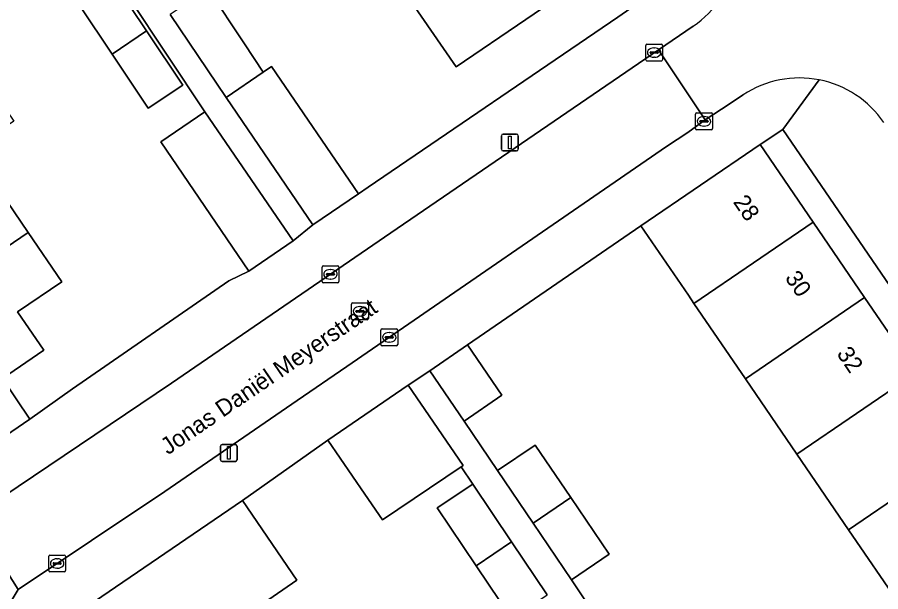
# Model space of a CAD drawing. Extents: x 157445 to 158888, y 383061 to 384688.
# Drawn here: x 158205.2 to 158256.4, y 383877.8 to 383911.9 of the extents above; entities that cross this region are included whole.
import ezdxf

# ---------------------------------------------------------------- set-up
doc = ezdxf.new("R2010")
doc.units = 0
for name, color, linetype in [('IMGEO_Erf', 7, 'Continuous'), ('IMGEO_Kolk', 7, 'Continuous'), ('IMGEO_Lichtmast', 7, 'Continuous'), ('IMGEO_Muur', 7, 'Continuous'), ('IMGEO_Openbare_ruimte_label', 7, 'Continuous'), ('IMGEO_Pand', 7, 'Continuous'), ('IMGEO_Pand_nummerreeks', 7, 'Continuous'), ('IMGEO_Rijbaan_lokaal_open', 7, 'Continuous'), ('IMGEO_Rioolput', 7, 'Continuous'), ('IMGEO_Voetpad_open', 7, 'Continuous')]:
    doc.layers.add(name, color=color, linetype=linetype)

msp = doc.modelspace()

# ---------------------------------------------------------------- linework, layer by layer
at = {"layer": 'IMGEO_Erf'}
for points in [[(158208.248, 383962.191), (158206.464, 383960.817), (158207.747, 383959.227), (158208.617, 383959.821), (158212.084, 383954.74), (158215.532, 383949.688), (158218.839, 383944.841), (158222.349, 383939.698), (158225.846, 383934.573), (158229.146, 383929.736), (158232.638, 383924.618), (158235.983, 383919.716), (158239.475, 383914.599), (158231.215, 383908.963), (158228.397, 383913.094), (158227.724, 383914.08), (158230.286, 383915.828), (158226.932, 383920.725), (158223.432, 383925.836), (158221.116, 383924.256), (158217.816, 383929.093), (158214.319, 383934.218)], [(158216.496, 383913.605), (158218.66, 383910.333), (158219.772, 383908.651), (158220.259, 383908.984), (158225.416, 383901.438), (158225.999, 383901.836), (158240.803, 383911.908), (158243.26, 383913.632)], [(158282.821, 383858.177), (158250.603, 383905.26), (158249.254, 383904.367), (158252.397, 383899.761), (158255.454, 383895.281), (158258.512, 383890.8)], [(158257.552, 383877.012), (158254.495, 383881.493), (158251.438, 383885.973), (158248.38, 383890.454), (158245.323, 383894.934), (158244.999, 383895.409), (158242.18, 383899.539), (158231.893, 383892.465), (158233.935, 383889.491), (158231.689, 383887.95), (158233.67, 383885.007), (158235.914, 383886.521), (158238.017, 383883.406), (158240.288, 383880.044), (158238.052, 383878.518), (158239.672, 383876.119)], [(158234.516, 383876.206), (158232.4, 383879.357), (158230.095, 383882.79), (158232.197, 383884.201), (158231.509, 383885.226), (158226.841, 383882.092), (158225.794, 383883.618), (158223.608, 383886.804), (158218.537, 383883.228), (158221.765, 383878.495), (158219.211, 383876.753)]]:
    msp.add_lwpolyline(points, dxfattribs=at)
for points in [[(158202.867, 383926.489), (158192.147, 383919.173), (158195.681, 383913.992), (158198.981, 383909.155), (158199.13, 383908.937), (158201.633, 383910.644), (158204.975, 383905.744), (158202.472, 383904.037), (158205.814, 383899.139), (158207.813, 383896.208), (158205.2, 383894.423), (158206.754, 383892.147), (158204.293, 383890.469), (158205.931, 383888.066), (158208.444, 383889.868), (158217.723, 383896.262), (158218.925, 383896.851), (158213.691, 383904.509), (158216.314, 383906.301)], [(158210.804, 383909.719), (158208.892, 383912.587), (158210.948, 383913.958), (158212.846, 383911.111), (158215.001, 383907.879), (158212.945, 383906.508)]]:
    msp.add_lwpolyline(points, close=True, dxfattribs=at)
at = {"layer": 'IMGEO_Kolk'}
for p, q in [((158242.465, 383909.389), (158242.465, 383910.241)), ((158242.54, 383910.315), (158243.392, 383910.315)), ((158242.953, 383910.095), (158242.978, 383910.095)), ((158243.466, 383910.241), (158243.466, 383909.389)), ((158242.724, 383909.809), (158242.724, 383909.821)), ((158243.162, 383909.772), (158242.764, 383909.772)), ((158242.767, 383909.858), (158243.165, 383909.858)), ((158242.976, 383909.535), (158242.951, 383909.535)), ((158243.208, 383909.821), (158243.208, 383909.809)), ((158243.392, 383909.315), (158242.54, 383909.315)), ((158245.42, 383905.308), (158245.42, 383906.16)), ((158245.495, 383906.234), (158246.347, 383906.234)), ((158245.722, 383905.777), (158246.12, 383905.777)), ((158245.908, 383906.014), (158245.933, 383906.014)), ((158246.421, 383906.16), (158246.421, 383905.308)), ((158245.679, 383905.728), (158245.679, 383905.74)), ((158246.117, 383905.691), (158245.719, 383905.691)), ((158245.931, 383905.454), (158245.906, 383905.454)), ((158246.163, 383905.74), (158246.163, 383905.728)), ((158246.347, 383905.234), (158245.495, 383905.234)), ((158223.258, 383896.231), (158223.258, 383897.083)), ((158223.333, 383897.157), (158224.185, 383897.157)), ((158224.259, 383897.083), (158224.259, 383896.231)), ((158223.517, 383896.651), (158223.517, 383896.663)), ((158223.955, 383896.614), (158223.557, 383896.614)), ((158223.56, 383896.7), (158223.958, 383896.7)), ((158223.746, 383896.937), (158223.771, 383896.937)), ((158224.001, 383896.663), (158224.001, 383896.651)), ((158224.185, 383896.157), (158223.333, 383896.157)), ((158223.769, 383896.377), (158223.744, 383896.377)), ((158226.746, 383892.49), (158226.746, 383893.342)), ((158226.821, 383893.416), (158227.673, 383893.416)), ((158227.048, 383892.959), (158227.446, 383892.959)), ((158227.234, 383893.196), (158227.259, 383893.196)), ((158227.747, 383893.342), (158227.747, 383892.49)), ((158227.005, 383892.91), (158227.005, 383892.922)), ((158227.443, 383892.873), (158227.045, 383892.873)), ((158227.257, 383892.636), (158227.232, 383892.636)), ((158227.489, 383892.922), (158227.489, 383892.91)), ((158227.673, 383892.416), (158226.821, 383892.416)), ((158207.042, 383879.071), (158207.042, 383879.923)), ((158207.117, 383879.997), (158207.969, 383879.997)), ((158207.53, 383879.777), (158207.555, 383879.777)), ((158208.043, 383879.923), (158208.043, 383879.071)), ((158207.301, 383879.491), (158207.301, 383879.503)), ((158207.739, 383879.454), (158207.341, 383879.454)), ((158207.344, 383879.54), (158207.742, 383879.54)), ((158207.553, 383879.217), (158207.528, 383879.217)), ((158207.785, 383879.503), (158207.785, 383879.491)), ((158207.969, 383878.997), (158207.117, 383878.997))]:
    msp.add_line(p, q, dxfattribs=at)
for points in [[(158242.465, 383909.389), (158242.465, 383910.241)], [(158242.54, 383910.315), (158243.392, 383910.315)], [(158243.466, 383910.241), (158243.466, 383909.389)], [(158243.392, 383909.315), (158242.54, 383909.315)], [(158245.42, 383905.308), (158245.42, 383906.16)], [(158245.495, 383906.234), (158246.347, 383906.234)], [(158246.421, 383906.16), (158246.421, 383905.308)], [(158246.347, 383905.234), (158245.495, 383905.234)], [(158223.258, 383896.231), (158223.258, 383897.083)], [(158223.333, 383897.157), (158224.185, 383897.157)], [(158224.259, 383897.083), (158224.259, 383896.231)], [(158224.185, 383896.157), (158223.333, 383896.157)], [(158226.746, 383892.49), (158226.746, 383893.342)], [(158226.821, 383893.416), (158227.673, 383893.416)], [(158227.747, 383893.342), (158227.747, 383892.49)], [(158227.673, 383892.416), (158226.821, 383892.416)], [(158207.042, 383879.071), (158207.042, 383879.923)], [(158207.117, 383879.997), (158207.969, 383879.997)], [(158208.043, 383879.923), (158208.043, 383879.071)], [(158207.969, 383878.997), (158207.117, 383878.997)]]:
    msp.add_lwpolyline(points, dxfattribs=at)
for centre, radius, start, end in [((158242.542, 383910.239), 0.0765, 91.552, 178.448), ((158242.542, 383910.239), 0.0765, 91.552, 178.448), ((158243.39, 383910.239), 0.0765, 1.552, 88.448), ((158243.39, 383910.239), 0.0765, 1.552, 88.448), ((158242.542, 383909.391), 0.0765, 181.552, 268.448), ((158242.542, 383909.391), 0.0765, 181.552, 268.448), ((158242.764, 383909.818), 0.0403, 85.8775, 175.7526), ((158242.761, 383909.808), 0.0366, 178.938, 274.7102), ((158243.165, 383909.815), 0.043, 264.8664, 352.4533), ((158243.169, 383909.82), 0.0386, 1.7309, 96.639), ((158243.39, 383909.391), 0.0765, 271.552, 358.448), ((158243.39, 383909.391), 0.0765, 271.552, 358.448), ((158245.497, 383906.158), 0.0765, 91.552, 178.448), ((158245.497, 383906.158), 0.0765, 91.552, 178.448), ((158245.719, 383905.737), 0.0403, 85.8775, 175.7526), ((158246.124, 383905.739), 0.0386, 1.7309, 96.639), ((158246.345, 383906.158), 0.0765, 1.552, 88.448), ((158246.345, 383906.158), 0.0765, 1.552, 88.448), ((158245.497, 383905.31), 0.0765, 181.552, 268.448), ((158245.497, 383905.31), 0.0765, 181.552, 268.448), ((158245.716, 383905.727), 0.0366, 178.938, 274.7102), ((158246.12, 383905.734), 0.043, 264.8664, 352.4533), ((158246.345, 383905.31), 0.0765, 271.552, 358.448), ((158246.345, 383905.31), 0.0765, 271.552, 358.448), ((158223.335, 383897.081), 0.0765, 91.552, 178.448), ((158223.335, 383897.081), 0.0765, 91.552, 178.448), ((158224.183, 383897.081), 0.0765, 1.552, 88.448), ((158224.183, 383897.081), 0.0765, 1.552, 88.448), ((158223.557, 383896.66), 0.0403, 85.8775, 175.7526), ((158223.554, 383896.65), 0.0366, 178.938, 274.7102), ((158223.958, 383896.657), 0.043, 264.8664, 352.4533), ((158223.962, 383896.662), 0.0386, 1.7309, 96.639), ((158223.335, 383896.233), 0.0765, 181.552, 268.448), ((158223.335, 383896.233), 0.0765, 181.552, 268.448), ((158224.183, 383896.233), 0.0765, 271.552, 358.448), ((158224.183, 383896.233), 0.0765, 271.552, 358.448), ((158226.823, 383893.34), 0.0765, 91.552, 178.448), ((158226.823, 383893.34), 0.0765, 91.552, 178.448), ((158227.045, 383892.919), 0.0403, 85.8775, 175.7526), ((158227.45, 383892.921), 0.0386, 1.7309, 96.639), ((158227.671, 383893.34), 0.0765, 1.552, 88.448), ((158227.671, 383893.34), 0.0765, 1.552, 88.448), ((158226.823, 383892.492), 0.0765, 181.552, 268.448), ((158226.823, 383892.492), 0.0765, 181.552, 268.448), ((158227.042, 383892.909), 0.0366, 178.938, 274.7102), ((158227.446, 383892.916), 0.043, 264.8664, 352.4533), ((158227.671, 383892.492), 0.0765, 271.552, 358.448), ((158227.671, 383892.492), 0.0765, 271.552, 358.448), ((158207.119, 383879.921), 0.0765, 91.552, 178.448), ((158207.119, 383879.921), 0.0765, 91.552, 178.448), ((158207.967, 383879.921), 0.0765, 1.552, 88.448), ((158207.967, 383879.921), 0.0765, 1.552, 88.448), ((158207.341, 383879.5), 0.0403, 85.8775, 175.7526), ((158207.338, 383879.49), 0.0366, 178.938, 274.7102), ((158207.742, 383879.497), 0.043, 264.8664, 352.4533), ((158207.746, 383879.502), 0.0386, 1.7309, 96.639), ((158207.119, 383879.073), 0.0765, 181.552, 268.448), ((158207.119, 383879.073), 0.0765, 181.552, 268.448), ((158207.967, 383879.073), 0.0765, 271.552, 358.448), ((158207.967, 383879.073), 0.0765, 271.552, 358.448)]:
    msp.add_arc(centre, radius, start, end, dxfattribs=at)
for centre, major_axis, ratio, start_param, end_param in [((158242.952, 383909.815), (-0.387, 0.002), 0.722429, 4.712389, 7.853982), ((158242.977, 383909.815), (-0.39, 0.002), 0.717154, 1.570796, 4.712389), ((158245.907, 383905.734), (-0.387, 0.002), 0.722429, 4.712389, 7.853982), ((158245.932, 383905.734), (-0.39, 0.002), 0.717154, 1.570796, 4.712389), ((158223.745, 383896.657), (-0.387, 0.002), 0.722429, 4.712389, 7.853982), ((158223.77, 383896.657), (-0.39, 0.002), 0.717154, 1.570796, 4.712389), ((158227.233, 383892.916), (-0.387, 0.002), 0.722429, 4.712389, 7.853982), ((158227.258, 383892.916), (-0.39, 0.002), 0.717154, 1.570796, 4.712389), ((158207.529, 383879.497), (-0.387, 0.002), 0.722429, 4.712389, 7.853982), ((158207.554, 383879.497), (-0.39, 0.002), 0.717154, 1.570796, 4.712389)]:
    msp.add_ellipse(centre, major_axis=major_axis, ratio=ratio, start_param=start_param, end_param=end_param, dxfattribs=at)
at = {"layer": 'IMGEO_Lichtmast'}
for p, q in [((158233.907, 383904.083), (158233.907, 383904.883)), ((158233.907, 383904.883), (158233.907, 383904.083)), ((158234.007, 383904.983), (158234.797, 383904.983)), ((158234.797, 383904.983), (158234.007, 383904.983)), ((158234.897, 383904.883), (158234.897, 383904.083)), ((158234.897, 383904.083), (158234.897, 383904.883)), ((158234.797, 383903.983), (158234.007, 383903.983)), ((158234.007, 383903.983), (158234.797, 383903.983)), ((158217.23, 383885.655), (158217.23, 383886.455)), ((158217.23, 383886.455), (158217.23, 383885.655)), ((158217.33, 383886.555), (158218.12, 383886.555)), ((158218.12, 383886.555), (158217.33, 383886.555)), ((158218.22, 383886.455), (158218.22, 383885.655)), ((158218.22, 383885.655), (158218.22, 383886.455)), ((158218.12, 383885.555), (158217.33, 383885.555)), ((158217.33, 383885.555), (158218.12, 383885.555))]:
    msp.add_line(p, q, dxfattribs=at)
for points in [[(158234.327, 383904.858), (158234.477, 383904.858), (158234.477, 383904.108), (158234.327, 383904.108), (158234.327, 383904.858)], [(158217.65, 383886.43), (158217.8, 383886.43), (158217.8, 383885.68), (158217.65, 383885.68), (158217.65, 383886.43)]]:
    msp.add_lwpolyline(points, dxfattribs=at)
for centre, start, end in [((158234.007, 383904.883), 90, 180), ((158234.007, 383904.883), 90, 180), ((158234.797, 383904.883), 0, 90), ((158234.797, 383904.883), 360, 90), ((158234.007, 383904.083), 180, 270), ((158234.007, 383904.083), 180, 270), ((158234.797, 383904.083), 270, 0), ((158234.797, 383904.083), 270, 0), ((158217.33, 383886.455), 90, 180), ((158217.33, 383886.455), 90, 180), ((158218.12, 383886.455), 0, 90), ((158218.12, 383886.455), 360, 90), ((158217.33, 383885.655), 180, 270), ((158217.33, 383885.655), 180, 270), ((158218.12, 383885.655), 270, 0), ((158218.12, 383885.655), 270, 0)]:
    msp.add_arc(centre, 0.1, start, end, dxfattribs=at)
at = {"layer": 'IMGEO_Muur'}
for points in [[(158225.999, 383901.836), (158240.803, 383911.908)], [(158208.444, 383889.868), (158217.723, 383896.262)]]:
    msp.add_lwpolyline(points, dxfattribs=at)
at = {"layer": 'IMGEO_Pand'}
for points in [[(158235.983, 383919.716), (158230.286, 383915.828), (158227.724, 383914.08), (158228.397, 383913.094), (158231.215, 383908.963), (158239.475, 383914.599)], [(158212.846, 383911.111), (158210.948, 383913.958), (158208.892, 383912.587), (158210.804, 383909.719)], [(158216.496, 383913.605), (158214.244, 383912.069), (158217.581, 383907.154), (158219.772, 383908.651), (158218.66, 383910.333)], [(158212.846, 383911.111), (158210.804, 383909.719), (158212.945, 383906.508), (158215.001, 383907.879)], [(158220.259, 383908.984), (158219.772, 383908.651), (158217.581, 383907.154), (158222.714, 383899.592), (158225.416, 383901.438)], [(158218.925, 383896.851), (158221.548, 383898.644), (158216.314, 383906.301), (158213.691, 383904.509)], [(158252.397, 383899.761), (158249.254, 383904.367), (158242.18, 383899.539), (158244.999, 383895.409), (158245.323, 383894.934)], [(158202.472, 383904.037), (158194.076, 383898.312), (158197.417, 383893.412), (158205.814, 383899.139)], [(158255.454, 383895.281), (158252.397, 383899.761), (158245.323, 383894.934), (158248.38, 383890.454)], [(158205.814, 383899.139), (158197.417, 383893.412), (158200.97, 383888.203), (158201.127, 383888.31), (158202.767, 383885.907), (158205.931, 383888.066), (158204.293, 383890.469), (158206.754, 383892.147), (158205.2, 383894.423), (158207.813, 383896.208)], [(158251.438, 383885.973), (158258.512, 383890.8), (158255.454, 383895.281), (158248.38, 383890.454)], [(158231.893, 383892.465), (158229.648, 383890.924), (158231.689, 383887.95), (158233.935, 383889.491)], [(158251.438, 383885.973), (158254.495, 383881.493), (158261.569, 383886.32), (158258.512, 383890.8)], [(158228.373, 383890.075), (158223.608, 383886.804), (158225.794, 383883.618), (158226.841, 383882.092), (158231.509, 383885.226), (158231.64, 383885.314)], [(158233.67, 383885.007), (158235.781, 383881.88), (158238.017, 383883.406), (158235.914, 383886.521)], [(158264.626, 383881.84), (158261.569, 383886.32), (158254.495, 383881.493), (158257.552, 383877.012)], [(158232.197, 383884.201), (158230.095, 383882.79), (158232.4, 383879.357), (158234.492, 383880.783)], [(158219.211, 383876.753), (158221.765, 383878.495), (158218.537, 383883.228), (158208.953, 383876.693), (158212.18, 383871.961)], [(158238.017, 383883.406), (158235.781, 383881.88), (158238.052, 383878.518), (158240.288, 383880.044)], [(158234.492, 383880.783), (158232.4, 383879.357), (158234.516, 383876.206), (158236.608, 383877.632)]]:
    msp.add_lwpolyline(points, close=True, dxfattribs=at)
at = {"layer": 'IMGEO_Rijbaan_lokaal_open'}
msp.add_lwpolyline([(158245.288, 383911.384), (158243.23, 383909.982), (158246, 383905.83), (158246.955, 383906.46), (158248.25, 383907.313)], dxfattribs=at)
msp.add_lwpolyline([(158221.792, 383889.169), (158224.74, 383891.195), (158243.701, 383904.239), (158244.954, 383905.077), (158246, 383905.83), (158243.23, 383909.982), (158227.34, 383899.111), (158220.295, 383894.284), (158214.323, 383890.192), (158202.489, 383882.225), (158203.861, 383880.09), (158205.233, 383877.954), (158213.929, 383883.767)], close=True, dxfattribs=at)
for centre, radius, start, end in [((158241.748, 383916.483), 6.208, 304.7709, 348.0503), ((158251.58, 383902.242), 6.067, 78.8372, 123.2931), ((158251.578, 383902.231), 6.078, 34.4596, 78.8387)]:
    msp.add_arc(centre, radius, start, end, dxfattribs=at)
at = {"layer": 'IMGEO_Rioolput'}
for p, q in [((158225.007, 383894.035), (158225.007, 383894.887)), ((158225.082, 383894.961), (158225.934, 383894.961)), ((158225.309, 383894.504), (158225.707, 383894.504)), ((158225.495, 383894.741), (158225.52, 383894.741)), ((158226.008, 383894.887), (158226.008, 383894.035)), ((158225.266, 383894.455), (158225.266, 383894.467)), ((158225.704, 383894.418), (158225.306, 383894.418)), ((158225.518, 383894.181), (158225.493, 383894.181)), ((158225.75, 383894.467), (158225.75, 383894.455)), ((158225.934, 383893.961), (158225.082, 383893.961))]:
    msp.add_line(p, q, dxfattribs=at)
for points in [[(158225.007, 383894.035), (158225.007, 383894.887)], [(158225.082, 383894.961), (158225.934, 383894.961)], [(158226.008, 383894.887), (158226.008, 383894.035)], [(158225.934, 383893.961), (158225.082, 383893.961)]]:
    msp.add_lwpolyline(points, dxfattribs=at)
for centre, radius, start, end in [((158225.084, 383894.885), 0.0765, 91.552, 178.448), ((158225.084, 383894.885), 0.0765, 91.552, 178.448), ((158225.306, 383894.464), 0.0403, 85.8775, 175.7526), ((158225.711, 383894.466), 0.0386, 1.7309, 96.639), ((158225.932, 383894.885), 0.0765, 1.552, 88.448), ((158225.932, 383894.885), 0.0765, 1.552, 88.448), ((158225.084, 383894.037), 0.0765, 181.552, 268.448), ((158225.084, 383894.037), 0.0765, 181.552, 268.448), ((158225.303, 383894.454), 0.0366, 178.938, 274.7102), ((158225.707, 383894.461), 0.043, 264.8664, 352.4533), ((158225.932, 383894.037), 0.0765, 271.552, 358.448), ((158225.932, 383894.037), 0.0765, 271.552, 358.448)]:
    msp.add_arc(centre, radius, start, end, dxfattribs=at)
for centre, major_axis, ratio, start_param, end_param in [((158225.494, 383894.461), (-0.387, 0.002), 0.722429, 4.712389, 7.853982), ((158225.519, 383894.461), (-0.39, 0.002), 0.717154, 1.570796, 4.712389)]:
    msp.add_ellipse(centre, major_axis=major_axis, ratio=ratio, start_param=start_param, end_param=end_param, dxfattribs=at)
at = {"layer": 'IMGEO_Voetpad_open'}
for points in [[(158202.867, 383926.489), (158216.314, 383906.301), (158221.548, 383898.644), (158222.714, 383899.592), (158217.581, 383907.154), (158214.244, 383912.069)], [(158243.26, 383913.632), (158240.803, 383911.908), (158225.999, 383901.836), (158225.416, 383901.438), (158222.714, 383899.592), (158221.548, 383898.644), (158218.925, 383896.851), (158217.723, 383896.262), (158208.444, 383889.868), (158205.931, 383888.066), (158202.767, 383885.907), (158201.719, 383885.01)], [(158243.23, 383909.982), (158245.288, 383911.384)], [(158198.625, 383885.156), (158198.023, 383885.701), (158200.692, 383881.905), (158202.489, 383882.225), (158214.323, 383890.192), (158220.295, 383894.284), (158227.34, 383899.111), (158243.23, 383909.982)], [(158231.893, 383892.465), (158242.18, 383899.539), (158249.254, 383904.367), (158250.603, 383905.26), (158252.755, 383908.194)], [(158252.755, 383908.194), (158250.603, 383905.26), (158282.821, 383858.177), (158283.568, 383857.085), (158314.406, 383812.02), (158315.08, 383810.811), (158315.198, 383810.6), (158319.462, 383804.339), (158323.13, 383799.314), (158327.979, 383792.222), (158330.843, 383787.992), (158333.261, 383790.767)], [(158248.25, 383907.313), (158246.955, 383906.46), (158246, 383905.83), (158244.954, 383905.077), (158243.701, 383904.239), (158224.74, 383891.195), (158221.792, 383889.169), (158213.929, 383883.767), (158205.233, 383877.954), (158204.324, 383876.428), (158205.651, 383874.482), (158208.953, 383876.693), (158218.537, 383883.228), (158223.608, 383886.804), (158228.373, 383890.075), (158229.648, 383890.924), (158231.893, 383892.465)], [(158239.672, 383876.119), (158238.052, 383878.518), (158235.781, 383881.88), (158233.67, 383885.007), (158231.689, 383887.95), (158229.648, 383890.924), (158228.373, 383890.075), (158231.64, 383885.314), (158231.509, 383885.226), (158232.197, 383884.201), (158234.492, 383880.783), (158236.608, 383877.632)], [(158220.561, 383852.622), (158219.571, 383854.073), (158205.651, 383874.482), (158204.324, 383876.428), (158205.233, 383877.954), (158203.861, 383880.09)]]:
    msp.add_lwpolyline(points, dxfattribs=at)
for centre, radius, start, end in [((158241.748, 383916.483), 6.208, 304.7709, 348.0503), ((158251.58, 383902.242), 6.067, 78.8372, 123.2931), ((158251.578, 383902.231), 6.078, 34.4596, 78.8387)]:
    msp.add_arc(centre, radius, start, end, dxfattribs=at)

# ---------------------------------------------------------------- texts
at = {"layer": 'IMGEO_Openbare_ruimte_label'}
msp.add_text('Jonas Daniël Meyerstraat', height=1, rotation=34.3256, dxfattribs=at).set_placement((158214.115, 383885.911))
at = {"layer": 'IMGEO_Pand_nummerreeks'}
for s, p in [('28', (158247.618, 383900.946)), ('30', (158250.692, 383896.441)), ('32', (158253.763, 383891.941))]:
    msp.add_text(s, height=1, rotation=304.3087, dxfattribs=at).set_placement(p)

doc.saveas('drawing.dxf')
